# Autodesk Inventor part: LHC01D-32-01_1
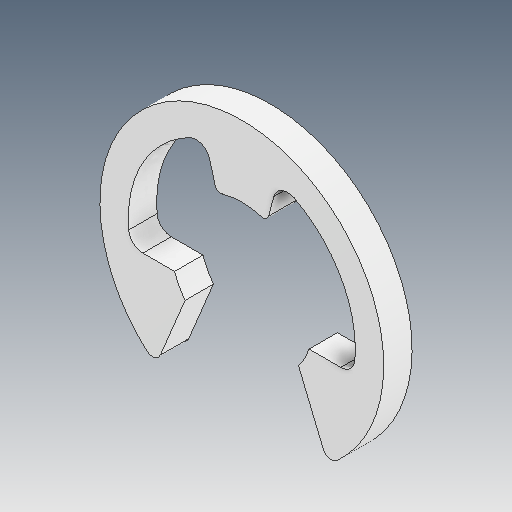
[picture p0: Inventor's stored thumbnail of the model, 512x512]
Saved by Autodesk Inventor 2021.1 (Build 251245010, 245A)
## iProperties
Created: 2021-05
Part Number: LHC01D-32-01_1
Material: Ogólny
Document SubType Name: Modeling
Designer: user
Density: 1 g/cm^3
Appearance: Domyślna
Author: user
Revision Number: ÈÎºÎ
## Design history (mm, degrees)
feature "ÊäÈë1"
node "Bryła1"
